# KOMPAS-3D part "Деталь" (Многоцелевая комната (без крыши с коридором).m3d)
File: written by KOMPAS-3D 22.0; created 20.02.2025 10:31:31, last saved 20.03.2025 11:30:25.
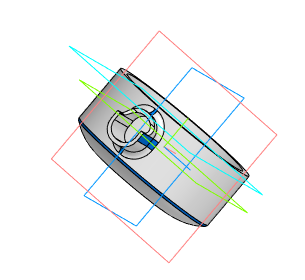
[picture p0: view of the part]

Document properties: Автор: Пользователь Windows; Полное имя файла: C:\Users\Student\Documents\Картошечка\База Сабнатика\Многоцелевая комната\Многоцелевая комната (без крыши с коридором).m3d

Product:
- Body: Тело 1
    Масса: 0.11405
- Part/product: Деталь
    Масса: 0.115416

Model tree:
1. Эскиз:3
2. Элемент вращения:1
     Угол 1 = 360
3. Скругление:1  (with: Элемент вращения:1)
     Радиус = 1
4. Эскиз:4  (with: Элемент вращения:1)
5. Элемент выдавливания:1
     Расстояние 2 = 6.1
6. Эскиз:5  (with: Элемент выдавливания:1)
7. Элемент выдавливания:2
     Расстояние 2 = 19
8. Смещенная плоскость:1
     Расстояние = 25
9. Эскиз:6
10. Элемент выдавливания:3
     Расстояние 1 = 10; Расстояние 2 = 4
11. Элемент выдавливания:4  (with: Элемент выдавливания:2)
     Расстояние 1 = 22
12. Эскиз:7
13. Элемент выдавливания:5
     Расстояние 2 = 10
14. Скругление:2  (with: Элемент выдавливания:3)
     Радиус = 2
15. Смещенная плоскость:2
     Расстояние = 7
16. Эскиз:8  (with: Элемент выдавливания:3)
17. Элемент выдавливания:6
     Расстояние 2 = 5.5
18. Скругление:3  (with: Элемент выдавливания:6)
     Радиус = 3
